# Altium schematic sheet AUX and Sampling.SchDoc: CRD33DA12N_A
size 431 x 279 mm; Date: 09.11.2024; Revision: 2; SheetNumber: 3; SheetTotal: 3; SheetSize: B
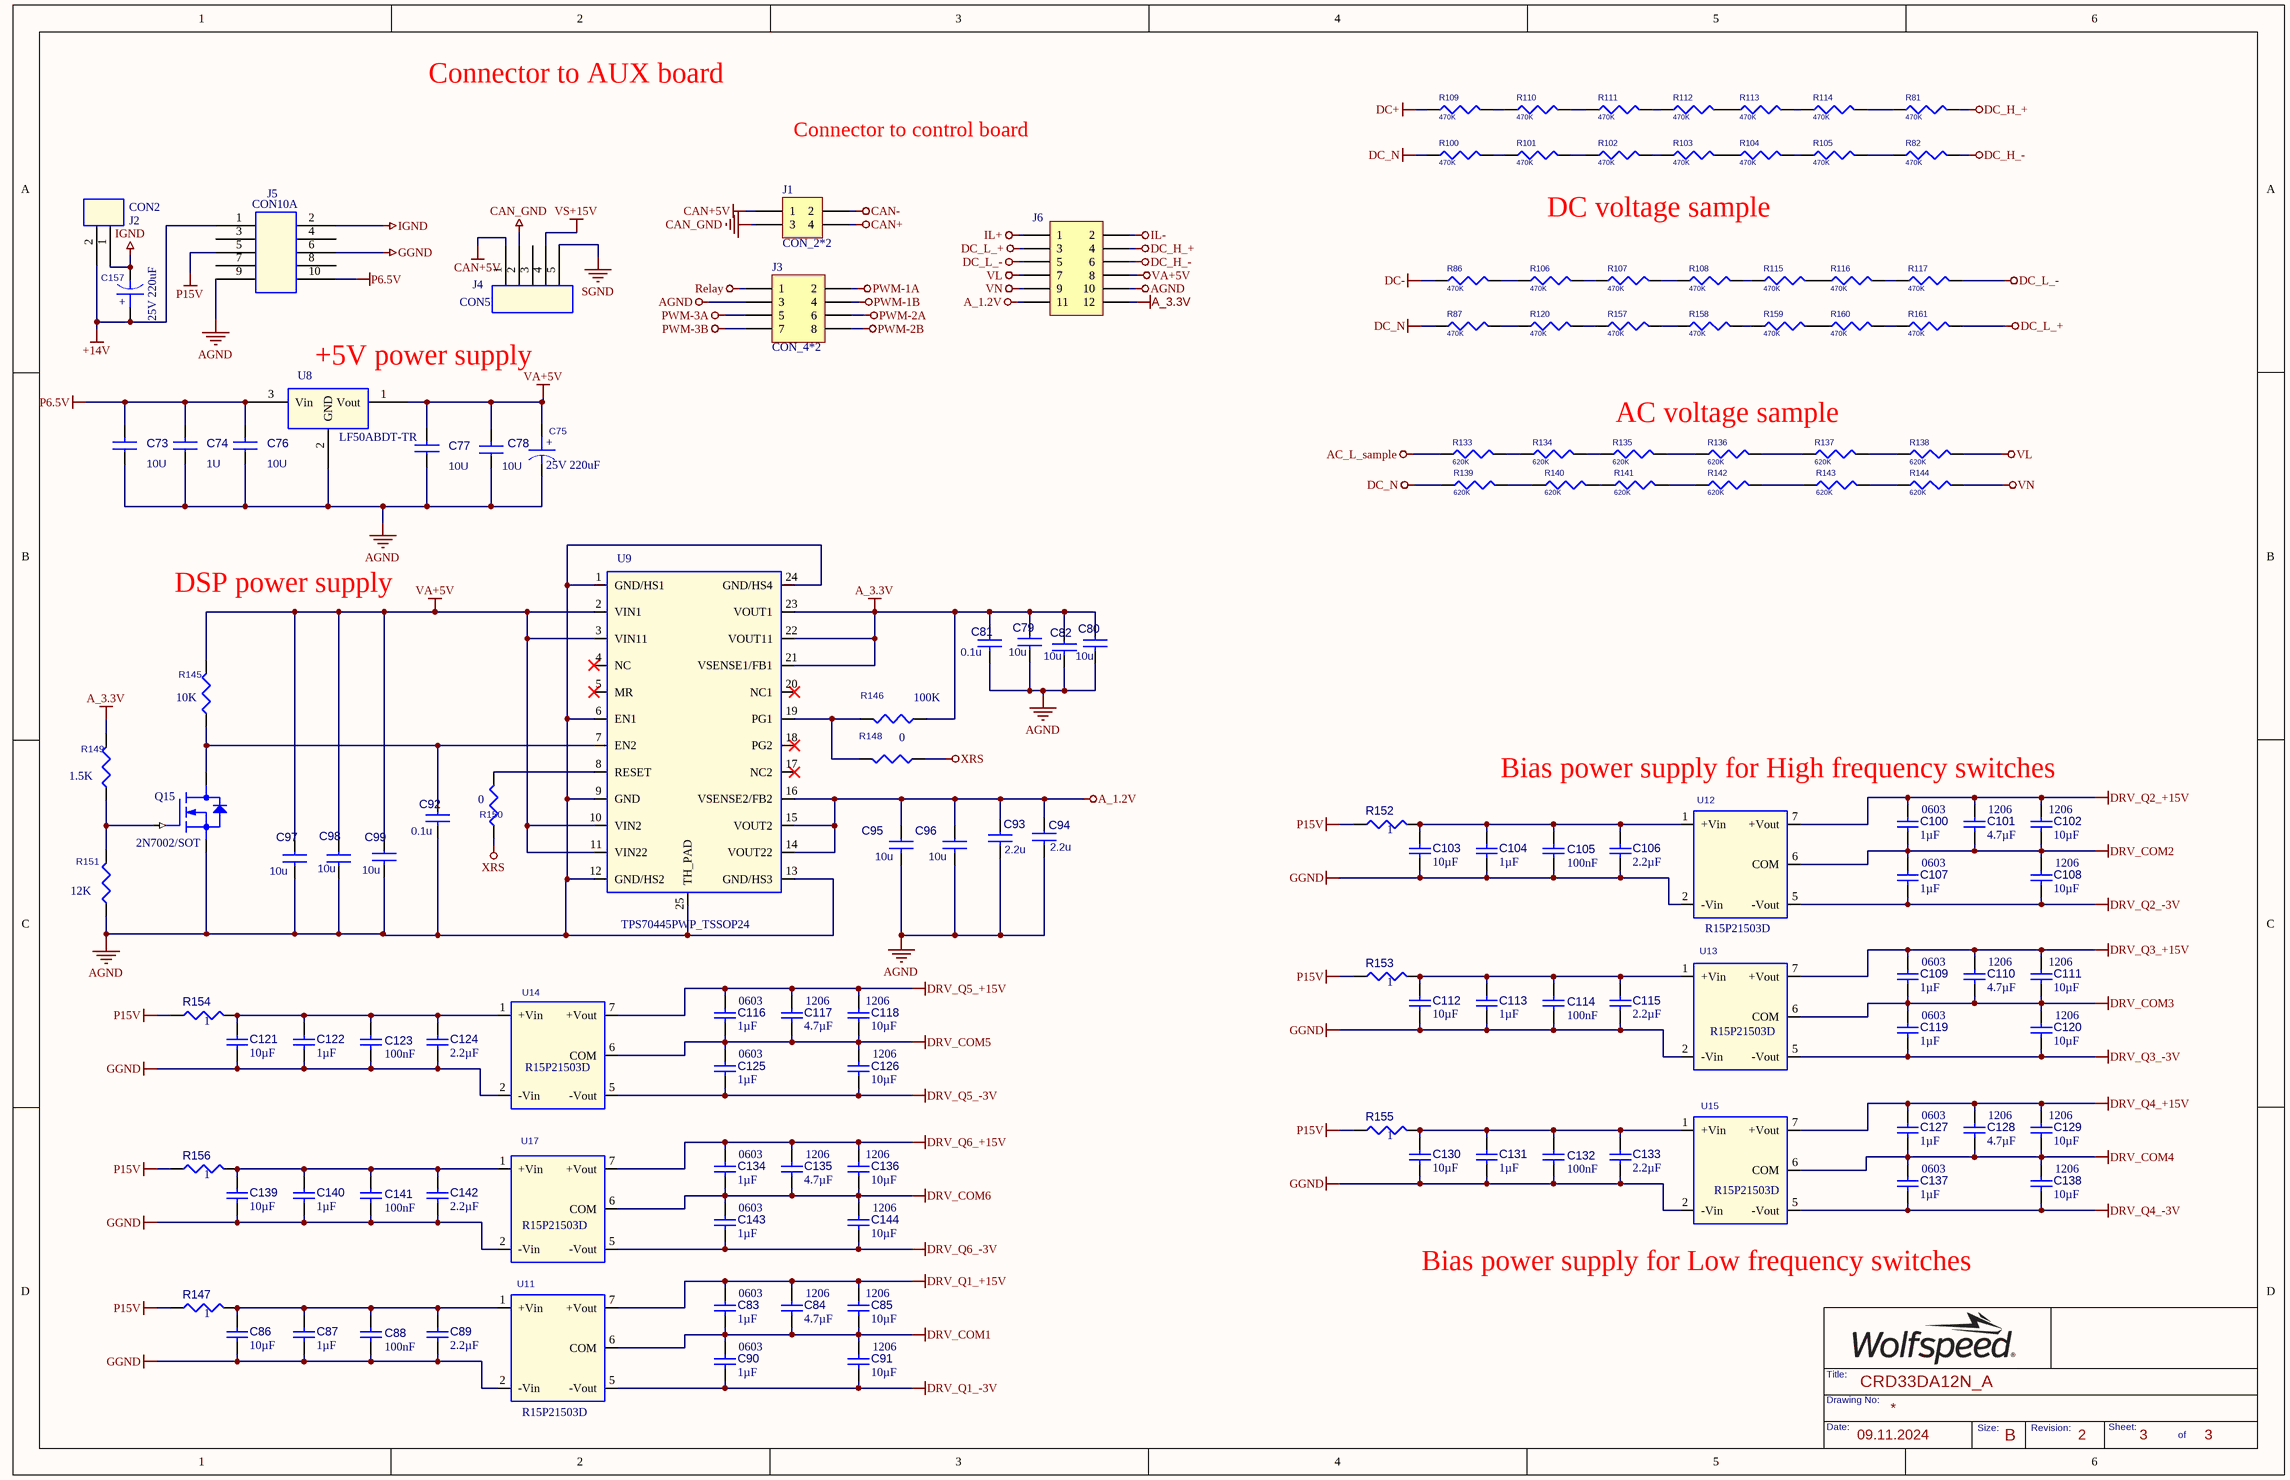
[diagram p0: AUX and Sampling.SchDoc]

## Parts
C73  10U  [C1206]
C74  1U  [C0603]
C75  25V 220uF  [ecap_d8p3_5]
C76  10U  [C1206]
C77  10U  [C1206]
C78  10U  [C1206]
C79  10u  [c1206]
C80  10u  [c1206]
C81  0.1u  [C0603]
C82  10u  [c1206]
C83  value 1µF  Case/Package: 0603  [FP-C0603C-CF-IPC_B]  (hidden comment: C1608X7R1V105K080AE)
C84  value 4.7µF  Case/Package: 1206  [CAPC3316X19N]  (hidden comment: C3216X7R1V475K160AB)
C85  value 10µF  Case/Package: 1206  [CAPC3316X19N]  (hidden comment: CMP-08246-001891-1)
C86  value 10µF  [CAPC3316X19N]  (hidden comment: CMP-08246-001891-1)
C87  value 1µF  [FP-C0603C-CF-IPC_B]  (hidden comment: C1608X7R1V105K080AE)
C88  value 100nF  [FP-C0603C-CF-IPC_B]  (hidden comment: C0603C104K5RAC7411)
C89  value 2.2µF  [CAPC2012X15N]  (hidden comment: C2012X7R1H225K125AC)
C90  value 1µF  Case/Package: 0603  [FP-C0603C-CF-IPC_B]  (hidden comment: C1608X7R1V105K080AE)
C91  value 10µF  Case/Package: 1206  [CAPC3316X19N]  (hidden comment: CMP-08246-001891-1)
C92  0.1u  [C0603]
C93  2.2u  [C0805]
C94  2.2u  [C0805]
C95  10u  [C1206]
C96  10u  [C1206]
C97  10u  [C1206]
C98  10u  [C1206]
C99  10u  [C1206]
C100  value 1µF  Case/Package: 0603  [FP-C0603C-CF-IPC_B]  (hidden comment: C1608X7R1V105K080AE)
C101  value 4.7µF  Case/Package: 1206  [CAPC3316X19N]  (hidden comment: C3216X7R1V475K160AB)
C102  value 10µF  Case/Package: 1206  [CAPC3316X19N]  (hidden comment: CMP-08246-001891-1)
C103  value 10µF  [CAPC3316X19N]  (hidden comment: CMP-08246-001891-1)
C104  value 1µF  [FP-C0603C-CF-IPC_B]  (hidden comment: C1608X7R1V105K080AE)
C105  value 100nF  [FP-C0603C-CF-IPC_B]  (hidden comment: C0603C104K5RAC7411)
C106  value 2.2µF  [CAPC2012X15N]  (hidden comment: C2012X7R1H225K125AC)
C107  value 1µF  Case/Package: 0603  [FP-C0603C-CF-IPC_B]  (hidden comment: C1608X7R1V105K080AE)
C108  value 10µF  Case/Package: 1206  [CAPC3316X19N]  (hidden comment: CMP-08246-001891-1)
C109  value 1µF  Case/Package: 0603  [FP-C0603C-CF-IPC_B]  (hidden comment: C1608X7R1V105K080AE)
C110  value 4.7µF  Case/Package: 1206  [CAPC3316X19N]  (hidden comment: C3216X7R1V475K160AB)
C111  value 10µF  Case/Package: 1206  [CAPC3316X19N]  (hidden comment: CMP-08246-001891-1)
C112  value 10µF  [CAPC3316X19N]  (hidden comment: CMP-08246-001891-1)
C113  value 1µF  [FP-C0603C-CF-IPC_B]  (hidden comment: C1608X7R1V105K080AE)
C114  value 100nF  [FP-C0603C-CF-IPC_B]  (hidden comment: C0603C104K5RAC7411)
C115  value 2.2µF  [CAPC2012X15N]  (hidden comment: C2012X7R1H225K125AC)
C116  value 1µF  Case/Package: 0603  [FP-C0603C-CF-IPC_B]  (hidden comment: C1608X7R1V105K080AE)
C117  value 4.7µF  Case/Package: 1206  [CAPC3316X19N]  (hidden comment: C3216X7R1V475K160AB)
C118  value 10µF  Case/Package: 1206  [CAPC3316X19N]  (hidden comment: CMP-08246-001891-1)
C119  value 1µF  Case/Package: 0603  [FP-C0603C-CF-IPC_B]  (hidden comment: C1608X7R1V105K080AE)
C120  value 10µF  Case/Package: 1206  [CAPC3316X19N]  (hidden comment: CMP-08246-001891-1)
C121  value 10µF  [CAPC3316X19N]  (hidden comment: CMP-08246-001891-1)
C122  value 1µF  [FP-C0603C-CF-IPC_B]  (hidden comment: C1608X7R1V105K080AE)
C123  value 100nF  [FP-C0603C-CF-IPC_B]  (hidden comment: C0603C104K5RAC7411)
C124  value 2.2µF  [CAPC2012X15N]  (hidden comment: C2012X7R1H225K125AC)
C125  value 1µF  Case/Package: 0603  [FP-C0603C-CF-IPC_B]  (hidden comment: C1608X7R1V105K080AE)
C126  value 10µF  Case/Package: 1206  [CAPC3316X19N]  (hidden comment: CMP-08246-001891-1)
C127  value 1µF  Case/Package: 0603  [FP-C0603C-CF-IPC_B]  (hidden comment: C1608X7R1V105K080AE)
C128  value 4.7µF  Case/Package: 1206  [CAPC3316X19N]  (hidden comment: C3216X7R1V475K160AB)
C129  value 10µF  Case/Package: 1206  [CAPC3316X19N]  (hidden comment: CMP-08246-001891-1)
C130  value 10µF  [CAPC3316X19N]  (hidden comment: CMP-08246-001891-1)
C131  value 1µF  [FP-C0603C-CF-IPC_B]  (hidden comment: C1608X7R1V105K080AE)
C132  value 100nF  [FP-C0603C-CF-IPC_B]  (hidden comment: C0603C104K5RAC7411)
C133  value 2.2µF  [CAPC2012X15N]  (hidden comment: C2012X7R1H225K125AC)
C134  value 1µF  Case/Package: 0603  [FP-C0603C-CF-IPC_B]  (hidden comment: C1608X7R1V105K080AE)
C135  value 4.7µF  Case/Package: 1206  [CAPC3316X19N]  (hidden comment: C3216X7R1V475K160AB)
C136  value 10µF  Case/Package: 1206  [CAPC3316X19N]  (hidden comment: CMP-08246-001891-1)
C137  value 1µF  Case/Package: 0603  [FP-C0603C-CF-IPC_B]  (hidden comment: C1608X7R1V105K080AE)
C138  value 10µF  Case/Package: 1206  [CAPC3316X19N]  (hidden comment: CMP-08246-001891-1)
C139  value 10µF  [CAPC3316X19N]  (hidden comment: CMP-08246-001891-1)
C140  value 1µF  [FP-C0603C-CF-IPC_B]  (hidden comment: C1608X7R1V105K080AE)
C141  value 100nF  [FP-C0603C-CF-IPC_B]  (hidden comment: C0603C104K5RAC7411)
C142  value 2.2µF  [CAPC2012X15N]  (hidden comment: C2012X7R1H225K125AC)
C143  value 1µF  Case/Package: 0603  [FP-C0603C-CF-IPC_B]  (hidden comment: C1608X7R1V105K080AE)
C144  value 10µF  Case/Package: 1206  [CAPC3316X19N]  (hidden comment: CMP-08246-001891-1)
C157  25V 220uF  [ecap_d8p3_5]
J1  CON_2*2  [HDR2X2H-254MM-90]
J2  CON2  [CON_5MM_2X1]
J3  CON_4*2  [HDR2X4H-254MM-90]
J4  CON5  [con_2mm54_5x1]
J5  CON10A  [con_2mm54_5x2]
J6  J10  [HDR2X6H-254MM-90]  (value not drawn)
Q15  2N7002/SOT  [SOT-23]
R81  470K  [1206]
R82  470K  [1206]
R86  470K  [1206]
R87  470K  [1206]
R100  470K  [1206]
R101  470K  [1206]
R102  470K  [1206]
R103  470K  [1206]
R104  470K  [1206]
R105  470K  [1206]
R106  470K  [1206]
R107  470K  [1206]
R108  470K  [1206]
R109  470K  [1206]
R110  470K  [1206]
R111  470K  [1206]
R112  470K  [1206]
R113  470K  [1206]
R114  470K  [1206]
R115  470K  [1206]
R116  470K  [1206]
R117  470K  [1206]
R120  470K  [1206]
R133  620K  [1206]
R134  620K  [1206]
R135  620K  [1206]
R136  620K  [1206]
R137  620K  [1206]
R138  620K  [1206]
R139  620K  [1206]
R140  620K  [1206]
R141  620K  [1206]
R142  620K  [1206]
R143  620K  [1206]
R144  620K  [1206]
R145  10K  [R0603]
R146  100K  [R0603]
R147  value 1  [RESC3015X06N]  (hidden comment: RMCF1206FT1R00)
R148  0  [R0603]
R149  1.5K  [R0603]
R150  0  [R0603]
R151  12K  [R0603]
R152  value 1  [RESC3015X06N]  (hidden comment: RMCF1206FT1R00)
R153  value 1  [RESC3015X06N]  (hidden comment: RMCF1206FT1R00)
R154  value 1  [RESC3015X06N]  (hidden comment: RMCF1206FT1R00)
R155  value 1  [RESC3015X06N]  (hidden comment: RMCF1206FT1R00)
R156  value 1  [RESC3015X06N]  (hidden comment: RMCF1206FT1R00)
R157  470K  [1206]
R158  470K  [1206]
R159  470K  [1206]
R160  470K  [1206]
R161  470K  [1206]
U8  LF50ABDT-TR  [TO252AB]
U9  TPS70445PWP_TSSOP24  [TSSOP24]
U11  R15P21503D  [g1212s_2w11]
U12  R15P21503D  [g1212s_2w11]
U13  R15P21503D  [g1212s_2w11]
U14  R15P21503D  [g1212s_2w11]
U15  R15P21503D  [g1212s_2w11]
U17  R15P21503D  [g1212s_2w11]

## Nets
+14V: C157.1 J2.2 J5.1
A_1.2V: C93.1 C94.1 C95.1 C96.1 J6.11 U9.14(VOUT22) U9.15(VOUT2) U9.16(VSENSE2/FB2)
A_3.3V: C79.1 C80.1 C81.1 C82.1 J6.12 R146.1 R149.2 U9.21(VSENSE1/FB1) U9.22(VOUT11) U9.23(VOUT1)
AC_L_sample: R133.1
AGND: C73.1 C74.1 C75.2 C76.1 C77.1 C78.1 C79.2 C80.2 C81.2 C82.2 C92.2 C93.2 C94.2 C95.2 C96.2 C97.2 C98.2 C99.2 J3.3 J5.9 J6.10 Q15.2(SOURCE) R151.1 U8.2(GND) U9.1(GND/HS1) U9.6(EN1) U9.9(GND) U9.12(GND/HS2) U9.13(GND/HS3) U9.24(GND/HS4) U9.25(TH_PAD)
CAN+: J1.4
CAN+5V: J1.1 J4.1
CAN-: J1.2
CAN_GND: J1.3 J4.2
DC+: R109.1
DC-: R86.1
DC_H_+: J6.4 R81.2
DC_H_-: J6.6 R82.2
DC_L_+: J6.3 R161.2
DC_L_-: J6.5 R117.2
DC_N: R87.1 R100.1 R139.1
DRV_COM1: C83.2 C84.1 C85.2 C90.1 C91.1 U11.6(COM)
DRV_COM2: C100.2 C101.1 C102.2 C107.1 C108.1 U12.6(COM)
DRV_COM3: C109.2 C110.1 C111.2 C119.1 C120.1 U13.6(COM)
DRV_COM4: C127.2 C128.1 C129.2 C137.1 C138.1 U15.6(COM)
DRV_COM5: C116.2 C117.1 C118.2 C125.1 C126.1 U14.6(COM)
DRV_COM6: C134.2 C135.1 C136.2 C143.1 C144.1 U17.6(COM)
DRV_Q1_+15V: C83.1 C84.2 C85.1 U11.7(+Vout)
DRV_Q1_-3V: C90.2 C91.2 U11.5(-Vout)
DRV_Q2_+15V: C100.1 C101.2 C102.1 U12.7(+Vout)
DRV_Q2_-3V: C107.2 C108.2 U12.5(-Vout)
DRV_Q3_+15V: C109.1 C110.2 C111.1 U13.7(+Vout)
DRV_Q3_-3V: C119.2 C120.2 U13.5(-Vout)
DRV_Q4_+15V: C127.1 C128.2 C129.1 U15.7(+Vout)
DRV_Q4_-3V: C137.2 C138.2 U15.5(-Vout)
DRV_Q5_+15V: C116.1 C117.2 C118.1 U14.7(+Vout)
DRV_Q5_-3V: C125.2 C126.2 U14.5(-Vout)
DRV_Q6_+15V: C134.1 C135.2 C136.1 U17.7(+Vout)
DRV_Q6_-3V: C143.2 C144.2 U17.5(-Vout)
GGND: C86.2 C87.2 C88.1 C89.2 C103.2 C104.2 C105.1 C106.2 C112.2 C113.2 C114.1 C115.2 C121.2 C122.2 C123.1 C124.2 C130.2 C131.2 C132.1 C133.2 C139.2 C140.2 C141.1 C142.2 J5.6 U11.2(-Vin) U12.2(-Vin) U13.2(-Vin) U14.2(-Vin) U15.2(-Vin) U17.2(-Vin)
IGND: C157.2 J2.1 J5.2
IL+: J6.1
IL-: J6.2
P6.5V: C73.2 C74.2 C76.2 J5.10 U8.3(Vin)
P15V: J5.5 R147.1 R152.1 R153.1 R154.1 R155.1 R156.1
PWM-1A: J3.2
PWM-1B: J3.4
PWM-2A: J3.6
PWM-2B: J3.8
PWM-3A: J3.5
PWM-3B: J3.7
Relay: J3.1
SGND: J4.5
VA+5V: C75.1 C77.2 C78.2 C97.1 C98.1 C99.1 J6.8 R145.2 U8.1(Vout) U9.2(VIN1) U9.3(VIN11) U9.10(VIN2) U9.11(VIN22)
VL: J6.7 R138.2
VN: J6.9 R144.2
VS+15V: J4.4
XRS: R148.1 R150.1
NetC86_1: C86.1 C87.1 C88.2 C89.1 R147.2 U11.1(+Vin)
NetC92_1: C92.1 Q15.3(DRAIN) R145.1 U9.7(EN2)
NetC103_1: C103.1 C104.1 C105.2 C106.1 R152.2 U12.1(+Vin)
NetC112_1: C112.1 C113.1 C114.2 C115.1 R153.2 U13.1(+Vin)
NetC121_1: C121.1 C122.1 C123.2 C124.1 R154.2 U14.1(+Vin)
NetC130_1: C130.1 C131.1 C132.2 C133.1 R155.2 U15.1(+Vin)
NetC139_1: C139.1 C140.1 C141.2 C142.1 R156.2 U17.1(+Vin)
NetQ15_1: Q15.1(GATE) R149.1 R151.2
NetR81_1: R81.1 R114.2
NetR82_1: R82.1 R105.2
NetR86_2: R86.2 R106.1
NetR87_2: R87.2 R120.1
NetR100_2: R100.2 R101.1
NetR101_2: R101.2 R102.1
NetR102_2: R102.2 R103.1
NetR103_2: R103.2 R104.1
NetR104_2: R104.2 R105.1
NetR106_2: R106.2 R107.1
NetR107_2: R107.2 R108.1
NetR108_2: R108.2 R115.1
NetR109_2: R109.2 R110.1
NetR110_2: R110.2 R111.1
NetR111_2: R111.2 R112.1
NetR112_2: R112.2 R113.1
NetR113_2: R113.2 R114.1
NetR115_2: R115.2 R116.1
NetR116_2: R116.2 R117.1
NetR120_2: R120.2 R157.1
NetR133_2: R133.2 R134.1
NetR134_2: R134.2 R135.1
NetR135_2: R135.2 R136.1
NetR136_2: R136.2 R137.1
NetR137_2: R137.2 R138.1
NetR139_2: R139.2 R140.1
NetR140_2: R140.2 R141.1
NetR141_2: R141.2 R142.1
NetR142_2: R142.2 R143.1
NetR143_2: R143.2 R144.1
NetR146_2: R146.2 R148.2 U9.19(PG1)
NetR150_2: R150.2 U9.8(RESET)
NetR157_2: R157.2 R158.1
NetR158_2: R158.2 R159.1
NetR159_2: R159.2 R160.1
NetR160_2: R160.2 R161.1

Not connected (* = marked no-connect by the designer): J4 3; J5 3 4 7 8; U9 4(NC)* 5(MR)* 17(NC2)* 18(PG2)* 20(NC1)*

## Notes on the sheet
- Connector to AUX board
- Connector to control board
- DC voltage sample
- (near U8) +5V power supply
- AC voltage sample
- DSP power supply
- Bias power supply for High frequency switches
- Bias power supply for Low frequency switches

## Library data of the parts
C73 C74 C76-C82 C92-C99 = CAP NP_Dup1
C75 C157 = CAP POL
C83 C87 C90 C100 C104 C107 C109 C113 C116 C119 C122 C125 C127 C131 C134 C137 C140 C143 = CMP-001-00097-9: Ceramic Capacitor, Multilayer, Ceramic, 35V, 10% +Tol, 10% -Tol, X7R, 15% TC, 1uF, Surface Mount, 0603
C84 C101 C110 C117 C128 C135 = CMP-001-00091-10: Ceramic Capacitor, Multilayer, Ceramic, 35V, 10% +Tol, 10% -Tol, X7R, 15% TC, 4.7uF, Surface Mount, 1206
C85 C86 C91 C102 C103 C108 C111 C112 C118 C120 C121 C126 C129 C130 C136 C138 C139 C144 = CMP-001-00083-11: Ceramic Capacitor, Multilayer, Ceramic, 50V, 10% +Tol, 10% -Tol, X7R, 15% TC, 10.0uF, Surface Mount, 1206
C88 C105 C114 C123 C132 C141 = CMP-001-00086-7: Ceramic Capacitor, Multilayer, Ceramic, 50V, 10% +Tol, 10% -Tol, X7R, 15% TC, 0.1uF, Surface Mount, 0603
C89 C106 C115 C124 C133 C142 = CMP-001-00093-6: Ceramic Capacitor, Multilayer, Ceramic, 50V, 10% +Tol, 10% -Tol, X7R, 15% TC, 2.2uF, Surface Mount, 0805
J6 = J10: 2*5P 1.27mm
R81 R82 R86 R87 R100-R117 R120 R157-R161 = RESISTOR_Dup1: RES SMD 470K OHM 1% 1/10W 1206; Manufacturer: Yageo; PCB Footprint: R1206; PN: AC1206FR-07470KL
R133-R144 = RESISTOR_Dup1: RES SMD 620K OHM 1% 1/10W 1206; Manufacturer: Yageo; PCB Footprint: R1206; PN: AC1206FR-07620KL
R145 R146 R148-R151 = RESISTOR_Dup1
R147 R152-R156 = CMP-009-00086-3: Fixed Resistor, Metal Glaze/thick Film, 0.25W, 1ohm, 200V, 1% +/-Tol, 200ppm/Cel, Surface Mount, 1206; Power: 250mW
U8 = MC78L05F-TP
U11-U15 U17 = E1212S-2WR2_3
